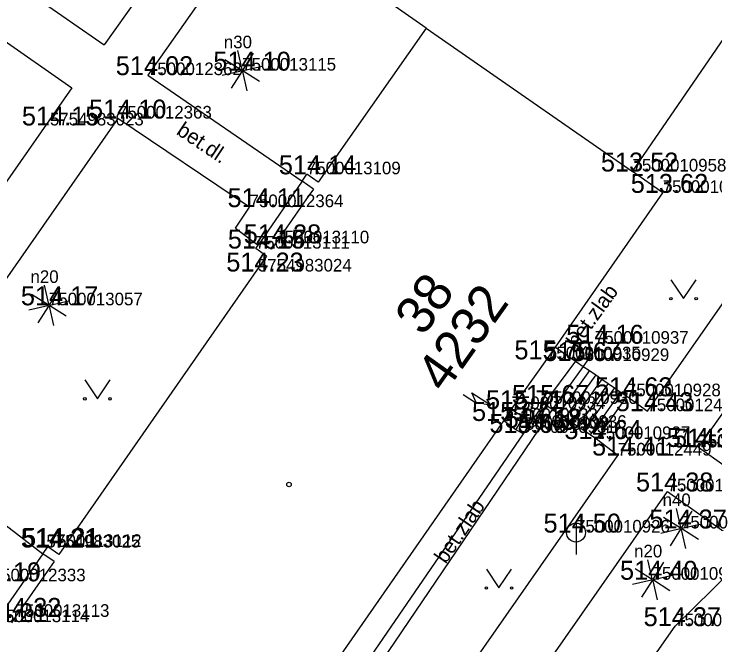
# Model space of a CAD drawing. Extents: x -669251 to -668549, y -1128351 to -1127698.
# Drawn here: x -668960.36 to -668932.59, y -1127946.39 to -1127921.39 of the extents above; entities that cross this region are included whole.
import ezdxf

# ---------------------------------------------------------------- set-up
doc = ezdxf.new("R2010")
doc.units = 0
for name, color, linetype in [('Vrstva 1', 7, 'Continuous'), ('Vrstva 10', 7, 'Continuous'), ('Vrstva 11', 7, 'Continuous'), ('Vrstva 2', 7, 'Continuous'), ('Vrstva 22', 7, 'Continuous'), ('Vrstva 24', 7, 'Continuous'), ('Vrstva 27', 7, 'Continuous'), ('Vrstva 3', 7, 'Continuous'), ('Vrstva 36', 7, 'Continuous'), ('Vrstva 40', 7, 'Continuous'), ('Vrstva 43', 7, 'Continuous'), ('Vrstva 44', 7, 'Continuous'), ('Vrstva 47', 7, 'Continuous'), ('Vrstva 5', 7, 'Continuous'), ('Vrstva 58', 7, 'Continuous'), ('Vrstva 6', 7, 'Continuous')]:
    doc.layers.add(name, color=color, linetype=linetype)

msp = doc.modelspace()

# ---------------------------------------------------------------- linework, layer by layer
at = {"layer": 'Vrstva 1'}
for p, q in [((-668951.319, -1127923.635), (-668951.319, -1127923.635)), ((-668955.055, -1127923.813), (-668955.055, -1127923.813)), ((-668956.243, -1127925.532), (-668956.243, -1127925.532)), ((-668958.939, -1127925.806), (-668958.939, -1127925.806)), ((-668935.858, -1127927.631), (-668935.858, -1127927.631)), ((-668948.759, -1127927.742), (-668948.759, -1127927.742)), ((-668934.661, -1127928.478), (-668934.661, -1127928.478)), ((-668951.028, -1127929.044), (-668951.028, -1127929.044)), ((-668950.78, -1127930.684), (-668950.78, -1127930.684)), ((-668950.008, -1127930.478), (-668950.008, -1127930.478)), ((-668950.7, -1127931.594), (-668950.7, -1127931.594)), ((-668958.979, -1127932.933), (-668958.979, -1127932.933)), ((-668937.351, -1127934.455), (-668937.351, -1127934.455)), ((-668939.248, -1127935.074), (-668939.248, -1127935.074)), ((-668938.121, -1127935.14), (-668938.121, -1127935.14)), ((-668936.079, -1127936.537), (-668936.079, -1127936.537)), ((-668939.369, -1127936.842), (-668939.369, -1127936.842)), ((-668940.648, -1127937.046), (-668940.648, -1127937.046)), ((-668935.267, -1127937.128), (-668935.267, -1127937.128)), ((-668940.95, -1127937.515), (-668940.95, -1127937.515)), ((-668940.486, -1127937.867), (-668940.486, -1127937.867)), ((-668939.81, -1127937.788), (-668939.81, -1127937.788)), ((-668940.24, -1127937.989), (-668940.24, -1127937.989)), ((-668937.29, -1127938.233), (-668937.29, -1127938.233)), ((-668933.251, -1127938.544), (-668933.251, -1127938.544)), ((-668933.238, -1127938.566), (-668933.238, -1127938.566)), ((-668936.445, -1127938.885), (-668936.445, -1127938.885)), ((-668934.469, -1127940.308), (-668934.469, -1127940.308)), ((-668933.936, -1127941.775), (-668933.936, -1127941.775)), ((-668938.096, -1127941.938), (-668938.096, -1127941.938)), ((-668959.078, -1127942.53), (-668959.078, -1127942.53)), ((-668959.026, -1127942.505), (-668959.026, -1127942.505)), ((-668935.065, -1127943.807), (-668935.065, -1127943.807)), ((-668960.3, -1127945.277), (-668960.3, -1127945.277)), ((-668934.167, -1127945.646), (-668934.167, -1127945.646))]:
    msp.add_line(p, q, dxfattribs=at)
at = {"layer": 'Vrstva 10'}
for p, q in [((-668947.848, -1127909.893), (-668956.786, -1127922.617)), ((-668946.11, -1127911.079), (-668955.055, -1127923.813)), ((-668962.136, -1127918.896), (-668956.786, -1127922.617)), ((-668963.314, -1127920.66), (-668958.065, -1127924.311)), ((-668935.267, -1127937.128), (-668925.942, -1127923.768)), ((-668955.055, -1127923.813), (-668948.948, -1127928.012)), ((-668958.065, -1127924.311), (-668966.842, -1127936.884)), ((-668933.238, -1127938.566), (-668923.838, -1127925.199)), ((-668956.243, -1127925.532), (-668965.131, -1127938.263)), ((-668951.028, -1127929.044), (-668956.243, -1127925.532)), ((-668951.587, -1127929.873), (-668951.028, -1127929.044)), ((-668951.587, -1127929.873), (-668950.686, -1127930.549)), ((-668937.726, -1127934.562), (-668938.121, -1127935.14)), ((-668937.726, -1127934.562), (-668937.417, -1127934.773)), ((-668937.417, -1127934.773), (-668937.813, -1127935.351)), ((-668936.079, -1127936.537), (-668935.267, -1127937.128)), ((-668939.036, -1127937.065), (-668947.956, -1127950.209)), ((-668948.347, -1127949.939), (-668940.177, -1127938.02)), ((-668936.445, -1127938.885), (-668937.29, -1127938.233)), ((-668965.131, -1127938.263), (-668959.214, -1127942.776)), ((-668929.563, -1127941.186), (-668933.238, -1127938.566)), ((-668945.547, -1127951.918), (-668936.445, -1127938.885)), ((-668943.593, -1127953.358), (-668934.469, -1127940.308)), ((-668934.469, -1127940.308), (-668931.154, -1127942.671)), ((-668934.167, -1127945.646), (-668931.154, -1127942.671)), ((-668940.958, -1127955.253), (-668934.167, -1127945.646))]:
    msp.add_line(p, q, dxfattribs=at)
at = {"layer": 'Vrstva 11'}
for p, q in [((-668938.912, -1127934.59), (-668938.121, -1127935.14)), ((-668938.121, -1127935.14), (-668939.369, -1127936.842)), ((-668938.121, -1127935.14), (-668937.813, -1127935.351)), ((-668937.813, -1127935.351), (-668939.036, -1127937.065)), ((-668937.813, -1127935.351), (-668937.565, -1127935.521)), ((-668937.565, -1127935.521), (-668938.787, -1127937.232)), ((-668937.317, -1127935.69), (-668938.537, -1127937.398)), ((-668937.565, -1127935.521), (-668937.317, -1127935.69)), ((-668937.317, -1127935.69), (-668937.07, -1127935.859)), ((-668937.07, -1127935.859), (-668938.288, -1127937.565)), ((-668937.07, -1127935.859), (-668936.822, -1127936.029)), ((-668936.822, -1127936.029), (-668938.038, -1127937.732)), ((-668936.574, -1127936.198), (-668937.789, -1127937.899)), ((-668936.822, -1127936.029), (-668936.574, -1127936.198)), ((-668936.574, -1127936.198), (-668936.327, -1127936.368)), ((-668936.327, -1127936.368), (-668937.539, -1127938.066)), ((-668936.079, -1127936.537), (-668937.29, -1127938.233)), ((-668936.327, -1127936.368), (-668936.079, -1127936.537)), ((-668940.177, -1127938.02), (-668939.369, -1127936.842)), ((-668939.036, -1127937.065), (-668939.369, -1127936.842)), ((-668938.787, -1127937.232), (-668939.036, -1127937.065)), ((-668938.537, -1127937.398), (-668938.787, -1127937.232)), ((-668938.288, -1127937.565), (-668938.537, -1127937.398)), ((-668940.486, -1127937.867), (-668940.95, -1127937.515)), ((-668938.038, -1127937.732), (-668938.288, -1127937.565)), ((-668940.177, -1127938.02), (-668940.486, -1127937.867)), ((-668937.789, -1127937.899), (-668938.038, -1127937.732)), ((-668937.539, -1127938.066), (-668937.789, -1127937.899)), ((-668937.29, -1127938.233), (-668937.539, -1127938.066))]:
    msp.add_line(p, q, dxfattribs=at)
at = {"layer": 'Vrstva 22'}
for p, q in [((-668951.327, -1127923.595), (-668951.499, -1127922.841)), ((-668950.885, -1127922.945), (-668951.299, -1127923.601)), ((-668951.353, -1127923.615), (-668952.009, -1127923.201)), ((-668951.279, -1127923.627), (-668950.525, -1127923.455)), ((-668952.113, -1127923.815), (-668951.359, -1127923.643)), ((-668951.339, -1127923.669), (-668951.753, -1127924.325)), ((-668951.311, -1127923.675), (-668951.139, -1127924.429)), ((-668950.629, -1127924.069), (-668951.285, -1127923.655)), ((-668958.987, -1127932.893), (-668959.159, -1127932.139)), ((-668958.545, -1127932.243), (-668958.959, -1127932.899)), ((-668959.013, -1127932.913), (-668959.669, -1127932.499)), ((-668959.773, -1127933.113), (-668959.019, -1127932.941)), ((-668958.289, -1127933.367), (-668958.945, -1127932.953)), ((-668958.939, -1127932.925), (-668958.185, -1127932.753)), ((-668958.999, -1127932.967), (-668959.413, -1127933.623)), ((-668958.971, -1127932.973), (-668958.799, -1127933.727)), ((-668933.944, -1127941.735), (-668934.116, -1127940.981)), ((-668933.502, -1127941.085), (-668933.916, -1127941.741)), ((-668933.97, -1127941.755), (-668934.626, -1127941.341)), ((-668934.73, -1127941.955), (-668933.976, -1127941.783)), ((-668933.956, -1127941.809), (-668934.37, -1127942.465)), ((-668933.928, -1127941.815), (-668933.756, -1127942.569)), ((-668933.246, -1127942.209), (-668933.902, -1127941.795)), ((-668933.896, -1127941.767), (-668933.142, -1127941.595)), ((-668935.073, -1127943.767), (-668935.245, -1127943.013)), ((-668934.631, -1127943.117), (-668935.045, -1127943.773)), ((-668935.099, -1127943.787), (-668935.755, -1127943.373)), ((-668935.025, -1127943.799), (-668934.271, -1127943.627)), ((-668935.859, -1127943.987), (-668935.105, -1127943.815)), ((-668935.085, -1127943.841), (-668935.499, -1127944.497)), ((-668935.057, -1127943.847), (-668934.885, -1127944.601)), ((-668934.375, -1127944.241), (-668935.031, -1127943.827))]:
    msp.add_line(p, q, dxfattribs=at)
for centre in [(-668951.319, -1127923.635), (-668958.979, -1127932.933), (-668933.936, -1127941.775), (-668935.065, -1127943.807)]:
    msp.add_circle(centre, 0.04, dxfattribs=at)
at = {"layer": 'Vrstva 24'}
for p, q in [((-668942.569, -1127936.472), (-668942.043, -1127936.811)), ((-668942.043, -1127936.811), (-668942.223, -1127936.398)), ((-668942.223, -1127936.398), (-668941.487, -1127936.872)), ((-668941.753, -1127936.832), (-668941.487, -1127936.872)), ((-668941.487, -1127936.872), (-668941.634, -1127936.647)), ((-668940.648, -1127937.046), (-668940.16, -1127937.36)), ((-668940.486, -1127937.867), (-668940.16, -1127937.36))]:
    msp.add_line(p, q, dxfattribs=at)
at = {"layer": 'Vrstva 27'}
msp.add_line((-668938.096, -1127941.563), (-668938.096, -1127942.813), dxfattribs=at)
msp.add_circle((-668938.096, -1127941.938), 0.375, dxfattribs=at)
at = {"layer": 'Vrstva 36'}
for p, q in [((-668934.336, -1127931.919), (-668933.836, -1127932.669)), ((-668933.836, -1127932.669), (-668933.336, -1127931.919)), ((-668957.558, -1127935.89), (-668957.058, -1127936.64)), ((-668957.058, -1127936.64), (-668956.558, -1127935.89)), ((-668941.648, -1127943.383), (-668941.148, -1127944.133)), ((-668941.148, -1127944.133), (-668940.648, -1127943.383))]:
    msp.add_line(p, q, dxfattribs=at)
for centre in [(-668934.336, -1127932.669), (-668933.336, -1127932.669), (-668957.557, -1127936.639), (-668956.557, -1127936.639), (-668941.647, -1127944.132), (-668940.647, -1127944.132)]:
    msp.add_circle(centre, 0.05, dxfattribs=at)
at = {"layer": 'Vrstva 5'}
for p, q in [((-668944.034, -1127921.95), (-668945.266, -1127921.095)), ((-668935.858, -1127927.631), (-668931.669, -1127921.512)), ((-668944.034, -1127921.95), (-668948.311, -1127928.056)), ((-668944.034, -1127921.95), (-668935.858, -1127927.631)), ((-668934.661, -1127928.478), (-668935.858, -1127927.631)), ((-668948.948, -1127928.012), (-668948.759, -1127927.742)), ((-668948.311, -1127928.056), (-668948.759, -1127927.742)), ((-668948.948, -1127928.012), (-668950.592, -1127930.413)), ((-668948.5, -1127928.326), (-668948.948, -1127928.012)), ((-668948.5, -1127928.326), (-668948.684, -1127928.588)), ((-668938.912, -1127934.59), (-668934.661, -1127928.478)), ((-668950.686, -1127930.549), (-668950.592, -1127930.413)), ((-668950.168, -1127930.708), (-668950.592, -1127930.413)), ((-668950.78, -1127930.684), (-668950.686, -1127930.549)), ((-668950.356, -1127930.979), (-668950.78, -1127930.684)), ((-668950.008, -1127930.478), (-668950.168, -1127930.708)), ((-668950.356, -1127930.979), (-668958.585, -1127942.811)), ((-668939.248, -1127935.074), (-668938.912, -1127934.59)), ((-668940.95, -1127937.515), (-668940.648, -1127937.046)), ((-668949.201, -1127949.344), (-668940.95, -1127937.515)), ((-668959.214, -1127942.776), (-668959.026, -1127942.505)), ((-668958.585, -1127942.811), (-668959.026, -1127942.505)), ((-668959.214, -1127942.776), (-668960.909, -1127945.215)), ((-668958.774, -1127943.082), (-668959.214, -1127942.776)), ((-668958.774, -1127943.082), (-668958.956, -1127943.345)), ((-668960.3, -1127945.277), (-668960.465, -1127945.518))]:
    msp.add_line(p, q, dxfattribs=at)
at = {"layer": 'Vrstva 58'}
msp.add_circle((-668949.466, -1127940.033), 0.0875, dxfattribs=at)
at = {"layer": 'Vrstva 6'}
for p, q in [((-668948.684, -1127928.588), (-668950.008, -1127930.478)), ((-668940.648, -1127937.046), (-668939.248, -1127935.074)), ((-668958.956, -1127943.345), (-668960.3, -1127945.277))]:
    msp.add_line(p, q, dxfattribs=at)

# ---------------------------------------------------------------- texts
at = {"layer": 'Vrstva 2'}
for s, p in [('7500013115', (-668951.319, -1127923.635)), ('7500012362', (-668955.055, -1127923.813)), ('7500012363', (-668956.243, -1127925.532)), ('5754983023', (-668958.939, -1127925.806)), ('7500010958', (-668935.858, -1127927.631)), ('7500013109', (-668948.759, -1127927.742)), ('7500010957', (-668934.661, -1127928.478)), ('7500012364', (-668951.028, -1127929.044)), ('7500013111', (-668950.78, -1127930.684)), ('7500013110', (-668950.008, -1127930.478)), ('5754983024', (-668950.7, -1127931.594)), ('7500013057', (-668958.979, -1127932.933)), ('7500010937', (-668937.351, -1127934.455)), ('7500010935', (-668939.248, -1127935.074)), ('7500010929', (-668938.121, -1127935.14)), ('7500010928', (-668936.079, -1127936.537)), ('7500010934', (-668940.648, -1127937.046)), ('7500010930', (-668939.369, -1127936.842)), ('7500012450', (-668935.267, -1127937.128)), ('7500010933', (-668940.95, -1127937.515)), ('7500010932', (-668940.486, -1127937.867)), ('7500010936', (-668939.81, -1127937.788)), ('7500010931', (-668940.24, -1127937.989)), ('7500010927', (-668937.29, -1127938.233)), ('7500012451', (-668933.251, -1127938.544)), ('7500012483', (-668933.238, -1127938.566)), ('7500012449', (-668936.445, -1127938.885)), ('7500012448', (-668934.469, -1127940.308)), ('7500010955', (-668933.936, -1127941.775)), ('7500010926', (-668938.096, -1127941.938)), ('5754983025', (-668959.078, -1127942.53)), ('7500013112', (-668959.026, -1127942.505)), ('7500012333', (-668961.243, -1127943.869)), ('7500010956', (-668935.065, -1127943.807)), ('7500013113', (-668960.3, -1127945.277)), ('7500013114', (-668961.095, -1127945.487)), ('7500012472', (-668934.167, -1127945.646))]:
    msp.add_text(s, height=0.5, dxfattribs=at).set_placement(p)
at = {"layer": 'Vrstva 3'}
for s, p in [('514.10 ', (-668952.465, -1127923.635)), ('514.02 ', (-668956.329, -1127923.813)), ('514.10 ', (-668957.389, -1127925.532)), ('514.15 ', (-668960.049, -1127925.806)), ('514.14 ', (-668949.869, -1127927.742)), ('513.52 ', (-668937.11, -1127927.631)), ('513.62 ', (-668935.927, -1127928.478)), ('514.11 ', (-668951.902, -1127929.044)), ('514.28 ', (-668951.26, -1127930.478)), ('514.15 ', (-668951.89, -1127930.684)), ('514.23 ', (-668951.952, -1127931.594)), ('514.17 ', (-668960.089, -1127932.933)), ('514.16 ', (-668938.484, -1127934.455)), ('515.70 ', (-668940.536, -1127935.074)), ('515.67 ', (-668939.387, -1127935.14)), ('514.63 ', (-668937.345, -1127936.537)), ('515.67 ', (-668940.635, -1127936.842)), ('515.71 ', (-668941.663, -1127937.046)), ('514.43 ', (-668936.519, -1127937.128)), ('515.67 ', (-668942.216, -1127937.515)), ('514.18 ', (-668940.92, -1127937.788)), ('515.66 ', (-668941.528, -1127937.989)), ('514.64 ', (-668938.556, -1127938.233)), ('514.33 ', (-668934.503, -1127938.544)), ('514.31 ', (-668934.253, -1127938.566)), ('514.41 ', (-668937.46, -1127938.885)), ('514.38 ', (-668935.721, -1127940.308)), ('514.50 ', (-668939.384, -1127941.938)), ('514.37 ', (-668935.188, -1127941.775)), ('514.21 ', (-668960.093, -1127942.53)), ('514.21 ', (-668960.041, -1127942.505)), ('514.19 ', (-668962.357, -1127943.869)), ('514.40 ', (-668936.353, -1127943.807)), ('514.32 ', (-668961.552, -1127945.277)), ('514.21 ', (-668962.11, -1127945.487)), ('514.37 ', (-668935.419, -1127945.646))]:
    msp.add_text(s, height=0.75, dxfattribs=at).set_placement(p)
at = {"layer": 'Vrstva 40'}
for s, rotation, p in [('bet.dl.', 326.3192, (-668953.965, -1127926.129)), ('bet.zlab', 54.1711, (-668938.04, -1127934.663)), ('bet.zlab', 55.841, (-668943.255, -1127943.207))]:
    msp.add_text(s, height=0.6, rotation=rotation, dxfattribs=at).set_placement(p)
at = {"layer": 'Vrstva 43'}
msp.add_text('4232', height=1.5, rotation=54.6276, dxfattribs=at).set_placement((-668943.293, -1127936.453))
at = {"layer": 'Vrstva 44'}
msp.add_text('38', height=1.5, rotation=54.6276, dxfattribs=at).set_placement((-668944.145, -1127934.197))
at = {"layer": 'Vrstva 47'}
for s, p in [('n30', (-668952.049, -1127922.749)), ('n20', (-668959.709, -1127932.047)), ('n40', (-668934.666, -1127940.889)), ('n20', (-668935.795, -1127942.921))]:
    msp.add_text(s, height=0.5, dxfattribs=at).set_placement(p)

doc.saveas('drawing.dxf')
